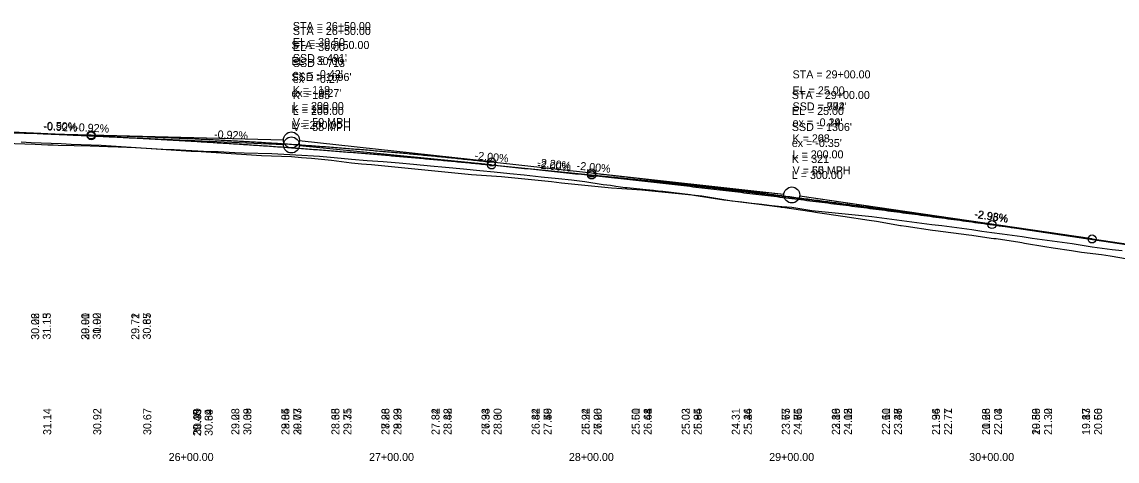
# Model space of a CAD drawing. Extents: x 3880794 to 3915434, y 287517 to 300173.
# Drawn here: x 3883054 to 3883601, y 296520 to 296739 of the extents above; entities that cross this region are included whole.
import ezdxf

# ---------------------------------------------------------------- set-up
doc = ezdxf.new("R2010")
doc.units = 0
for name, color, linetype in [('Level 1', 7, 'Continuous'), ('Level 2', 7, 'Continuous'), ('Level 30', 7, 'Continuous'), ('Level 31', 7, 'Continuous'), ('Level 32', 7, 'Continuous')]:
    doc.layers.add(name, color=color, linetype=linetype)

msp = doc.modelspace()

# ---------------------------------------------------------------- linework, layer by layer
at = {"layer": 'Level 1'}
for p, q in [((3882738.3, 296691.51), (3883088.3, 296682.76)), ((3883088.3, 296682.34), (3882892.29, 296691.32)), ((3883088.3, 296682.76), (3883184.3, 296680.36)), ((3883088.3, 296682.34), (3883184.3, 296677.94)), ((3883288.3, 296669.26), (3883192.27, 296679.82)), ((3883288.3, 296667.76), (3883192.28, 296677.36)), ((3883288.3, 296669.26), (3883338.3, 296663.76)), ((3883288.3, 296667.76), (3883434.32, 296653.16)), ((3883338.3, 296663.76), (3883434.32, 296653.19)), ((3883588.3, 296630.76), (3883442.25, 296652.18)), ((3883538.3, 296637.96), (3883442.25, 296652.17)), ((3883538.3, 296637.96), (3883838.3, 296593.56)), ((3883588.3, 296630.76), (3883838.3, 296594.09))]:
    msp.add_line(p, q, dxfattribs=at)
for points in [[(3883044.95, 296678.6), (3883060.37, 296678.16), (3883066.58, 296677.9), (3883069.37, 296677.82), (3883071.73, 296677.72), (3883087.79, 296677.27), (3883096.62, 296676.93), (3883101.73, 296676.79), (3883110.49, 296676.45), (3883126.78, 296675.58), (3883129.78, 296675.47), (3883147.36, 296674.53)], [(3883147.36, 296674.53), (3883151.71, 296674.52), (3883159.98, 296674.07), (3883164.76, 296673.8), (3883178.49, 296673.55), (3883184.5, 296673.22), (3883190.45, 296672.9), (3883202.4, 296672.11), (3883209.69, 296671.5), (3883218.25, 296670.64), (3883226.17, 296669.98), (3883234.22, 296669.43), (3883242.1, 296668.86), (3883249.28, 296668.2), (3883257.77, 296667.37), (3883265.3, 296666.68), (3883274.32, 296665.85), (3883282.48, 296665.06), (3883289.67, 296664.32), (3883297.39, 296663.48), (3883304.57, 296662.78), (3883313.02, 296661.87), (3883321.71, 296661.06), (3883328.28, 296660.34), (3883334.9, 296659.47), (3883344.06, 296658.03), (3883347.79, 296657.62), (3883350.39, 296657.19), (3883354.97, 296656.56), (3883356.1, 296656.47), (3883365.47, 296655.51), (3883369.23, 296655.18), (3883370.2, 296655.02), (3883371.5, 296654.87), (3883373.81, 296654.65), (3883387.76, 296652.97), (3883389.35, 296652.74), (3883404.31, 296650.42), (3883405.95, 296650.21), (3883419.36, 296648.54), (3883420.71, 296648.42), (3883432.28, 296646.87), (3883432.97, 296646.72), (3883433.28, 296646.69), (3883433.62, 296646.68), (3883448.27, 296644.59), (3883451.1, 296644), (3883463.76, 296642.16), (3883476.86, 296640.13), (3883480.52, 296639.63), (3883492.55, 296637.58), (3883492.91, 296637.53), (3883495.39, 296637.19), (3883508.51, 296635.16), (3883510.04, 296634.96), (3883526.73, 296632.91), (3883528.26, 296632.7), (3883537.81, 296631.24), (3883539.26, 296631.04), (3883540.32, 296630.93), (3883552.14, 296629.21), (3883553.22, 296629.03), (3883554.53, 296628.75), (3883564.71, 296626.94), (3883568.83, 296626.35), (3883577.96, 296624.98), (3883583.07, 296624.19), (3883592.97, 296623.06), (3883597.27, 296622.38), (3883605.94, 296620.85)]]:
    msp.add_lwpolyline(points, dxfattribs=at)
for centre in [(3883188.3, 296680.26), (3883188.3, 296677.76), (3883438.3, 296652.76), (3883438.3, 296652.76)]:
    msp.add_circle(centre, 4, dxfattribs=at)
for points in [[(3882688.3, 296694.36), (3882696.3, 296694.25), (3882704.3, 296694.13), (3882712.3, 296694), (3882720.3, 296693.87), (3882728.3, 296693.73), (3882736.3, 296693.59), (3882744.3, 296693.44), (3882752.3, 296693.29), (3882760.3, 296693.13), (3882768.3, 296692.97), (3882776.3, 296692.8), (3882784.3, 296692.63), (3882792.3, 296692.45), (3882800.3, 296692.27), (3882808.3, 296692.08), (3882816.3, 296691.89), (3882824.3, 296691.69), (3882832.3, 296691.49), (3882840.3, 296691.28), (3882848.3, 296691.07), (3882856.3, 296690.85), (3882864.3, 296690.63), (3882872.3, 296690.4), (3882880.3, 296690.17), (3882888.3, 296689.93), (3882896.3, 296689.69), (3882904.3, 296689.44), (3882912.3, 296689.19), (3882920.3, 296688.93), (3882928.3, 296688.66), (3882936.3, 296688.4), (3882944.3, 296688.12), (3882952.3, 296687.84), (3882960.3, 296687.56), (3882968.3, 296687.27), (3882976.3, 296686.98), (3882984.3, 296686.68), (3882992.3, 296686.38), (3883000.3, 296686.07), (3883008.3, 296685.75), (3883016.3, 296685.44), (3883024.3, 296685.11), (3883032.3, 296684.78), (3883040.3, 296684.45), (3883048.3, 296684.11), (3883056.3, 296683.77), (3883064.3, 296683.42), (3883072.3, 296683.06), (3883080.3, 296682.7), (3883088.3, 296682.34)], [(3883088.3, 296682.76), (3883092.3, 296682.65), (3883096.3, 296682.54), (3883100.3, 296682.43), (3883104.3, 296682.3), (3883108.3, 296682.17), (3883112.3, 296682.03), (3883116.3, 296681.89), (3883120.3, 296681.74), (3883124.3, 296681.58), (3883128.3, 296681.42), (3883132.3, 296681.25), (3883136.3, 296681.07), (3883140.3, 296680.88), (3883144.3, 296680.69), (3883148.3, 296680.49), (3883152.3, 296680.29), (3883156.3, 296680.07), (3883160.3, 296679.86), (3883164.3, 296679.63), (3883168.3, 296679.4), (3883172.3, 296679.16), (3883176.3, 296678.91), (3883180.3, 296678.66), (3883184.3, 296678.4), (3883188.3, 296678.13), (3883192.3, 296677.86), (3883196.3, 296677.58), (3883200.3, 296677.29), (3883204.3, 296677), (3883208.3, 296676.7), (3883212.3, 296676.39), (3883216.3, 296676.08), (3883220.3, 296675.75), (3883224.3, 296675.43), (3883228.3, 296675.09), (3883232.3, 296674.75), (3883236.3, 296674.4), (3883240.3, 296674.05), (3883244.3, 296673.69), (3883248.3, 296673.32), (3883252.3, 296672.94), (3883256.3, 296672.56), (3883260.3, 296672.17), (3883264.3, 296671.77), (3883268.3, 296671.37), (3883272.3, 296670.96), (3883276.3, 296670.55), (3883280.3, 296670.12), (3883284.3, 296669.69), (3883288.3, 296669.26)], [(3883088.3, 296682.34), (3883092.3, 296682.15), (3883096.3, 296681.96), (3883100.3, 296681.77), (3883104.3, 296681.57), (3883108.3, 296681.37), (3883112.3, 296681.16), (3883116.3, 296680.95), (3883120.3, 296680.73), (3883124.3, 296680.51), (3883128.3, 296680.29), (3883132.3, 296680.06), (3883136.3, 296679.83), (3883140.3, 296679.59), (3883144.3, 296679.35), (3883148.3, 296679.1), (3883152.3, 296678.85), (3883156.3, 296678.6), (3883160.3, 296678.34), (3883164.3, 296678.07), (3883168.3, 296677.81), (3883172.3, 296677.53), (3883176.3, 296677.26), (3883180.3, 296676.98), (3883184.3, 296676.69), (3883188.3, 296676.4), (3883192.3, 296676.11), (3883196.3, 296675.81), (3883200.3, 296675.51), (3883204.3, 296675.2), (3883208.3, 296674.89), (3883212.3, 296674.57), (3883216.3, 296674.25), (3883220.3, 296673.93), (3883224.3, 296673.6), (3883228.3, 296673.27), (3883232.3, 296672.93), (3883236.3, 296672.59), (3883240.3, 296672.24), (3883244.3, 296671.89), (3883248.3, 296671.54), (3883252.3, 296671.18), (3883256.3, 296670.82), (3883260.3, 296670.45), (3883264.3, 296670.08), (3883268.3, 296669.7), (3883272.3, 296669.32), (3883276.3, 296668.94), (3883280.3, 296668.55), (3883284.3, 296668.15), (3883288.3, 296667.76)], [(3883288.3, 296667.76), (3883294.3, 296667.15), (3883300.3, 296666.55), (3883306.3, 296665.93), (3883312.3, 296665.31), (3883318.3, 296664.69), (3883324.3, 296664.06), (3883330.3, 296663.42), (3883336.3, 296662.78), (3883342.3, 296662.13), (3883348.3, 296661.48), (3883354.3, 296660.82), (3883360.3, 296660.15), (3883366.3, 296659.48), (3883372.3, 296658.81), (3883378.3, 296658.13), (3883384.3, 296657.44), (3883390.3, 296656.75), (3883396.3, 296656.05), (3883402.3, 296655.35), (3883408.3, 296654.64), (3883414.3, 296653.92), (3883420.3, 296653.2), (3883426.3, 296652.48), (3883432.3, 296651.74), (3883438.3, 296651.01), (3883444.3, 296650.26), (3883450.3, 296649.52), (3883456.3, 296648.76), (3883462.3, 296648), (3883468.3, 296647.24), (3883474.3, 296646.47), (3883480.3, 296645.69), (3883486.3, 296644.91), (3883492.3, 296644.12), (3883498.3, 296643.33), (3883504.3, 296642.53), (3883510.3, 296641.72), (3883516.3, 296640.91), (3883522.3, 296640.1), (3883528.3, 296639.28), (3883534.3, 296638.45), (3883540.3, 296637.62), (3883546.3, 296636.78), (3883552.3, 296635.94), (3883558.3, 296635.09), (3883564.3, 296634.23), (3883570.3, 296633.37), (3883576.3, 296632.51), (3883582.3, 296631.63), (3883588.3, 296630.76)], [(3883338.3, 296663.76), (3883342.3, 296663.32), (3883346.3, 296662.87), (3883350.3, 296662.42), (3883354.3, 296661.97), (3883358.3, 296661.52), (3883362.3, 296661.06), (3883366.3, 296660.6), (3883370.3, 296660.14), (3883374.3, 296659.67), (3883378.3, 296659.2), (3883382.3, 296658.73), (3883386.3, 296658.26), (3883390.3, 296657.78), (3883394.3, 296657.3), (3883398.3, 296656.81), (3883402.3, 296656.33), (3883406.3, 296655.84), (3883410.3, 296655.34), (3883414.3, 296654.85), (3883418.3, 296654.35), (3883422.3, 296653.85), (3883426.3, 296653.34), (3883430.3, 296652.83), (3883434.3, 296652.32), (3883438.3, 296651.81), (3883442.3, 296651.29), (3883446.3, 296650.77), (3883450.3, 296650.25), (3883454.3, 296649.72), (3883458.3, 296649.19), (3883462.3, 296648.66), (3883466.3, 296648.12), (3883470.3, 296647.58), (3883474.3, 296647.04), (3883478.3, 296646.49), (3883482.3, 296645.95), (3883486.3, 296645.4), (3883490.3, 296644.84), (3883494.3, 296644.29), (3883498.3, 296643.72), (3883502.3, 296643.16), (3883506.3, 296642.6), (3883510.3, 296642.03), (3883514.3, 296641.45), (3883518.3, 296640.88), (3883522.3, 296640.3), (3883526.3, 296639.72), (3883530.3, 296639.13), (3883534.3, 296638.55), (3883538.3, 296637.96)]]:
    msp.add_spline(points, degree=3, dxfattribs=at)
at = {"layer": 'Level 2'}
for p, q in [((3883038.3, 296684.63), (3883088.3, 296682.34)), ((3883088.3, 296682.34), (3883184.3, 296677.94)), ((3883288.3, 296667.76), (3883192.28, 296677.36)), ((3883288.3, 296667.76), (3883338.3, 296662.76)), ((3883338.3, 296662.76), (3883434.32, 296653.16)), ((3883538.3, 296637.96), (3883442.25, 296652.17)), ((3883538.3, 296637.96), (3883838.3, 296593.56))]:
    msp.add_line(p, q, dxfattribs=at)
for points in [[(3883053.3, 296679.3), (3883058.3, 296679.08), (3883063.3, 296678.87), (3883068.3, 296678.66), (3883073.3, 296678.44), (3883078.3, 296678.22), (3883083.3, 296678.01), (3883088.3, 296677.8), (3883093.3, 296677.59), (3883098.3, 296677.33), (3883103.3, 296677.01), (3883108.3, 296676.69), (3883113.3, 296676.37), (3883118.3, 296676.05), (3883123.3, 296675.72), (3883128.3, 296675.4), (3883133.3, 296675.07), (3883138.3, 296674.75), (3883143.3, 296674.43), (3883148.3, 296674.1), (3883153.3, 296673.78), (3883158.3, 296673.46), (3883163.3, 296673.14), (3883168.3, 296672.82), (3883173.3, 296672.53), (3883178.3, 296672.34), (3883183.3, 296672.16), (3883188.3, 296671.96), (3883193.3, 296671.54), (3883198.3, 296671.12), (3883203.3, 296670.7), (3883208.3, 296670.13), (3883213.3, 296669.51), (3883218.3, 296668.9), (3883223.3, 296668.35), (3883228.3, 296667.93), (3883233.3, 296667.5), (3883238.3, 296667.08), (3883243.3, 296666.58), (3883248.3, 296666.05), (3883253.3, 296665.52), (3883258.3, 296665), (3883263.3, 296664.48), (3883268.3, 296663.96), (3883273.3, 296663.44), (3883278.3, 296663.09), (3883283.3, 296662.74), (3883288.3, 296662.39), (3883293.3, 296661.97), (3883298.3, 296661.47), (3883303.3, 296660.98), (3883308.3, 296660.48), (3883313.3, 296659.96), (3883318.3, 296659.43), (3883323.3, 296658.89), (3883328.3, 296658.36), (3883333.3, 296657.85), (3883338.3, 296657.35), (3883343.3, 296656.85), (3883348.3, 296656.35), (3883353.3, 296655.99), (3883358.3, 296655.68), (3883363.3, 296655.3), (3883368.3, 296654.84), (3883373.3, 296654.37), (3883378.3, 296653.89), (3883383.3, 296653.38), (3883388.3, 296652.88), (3883393.3, 296652.32), (3883398.3, 296651.51), (3883403.3, 296650.69), (3883408.3, 296649.92), (3883413.3, 296649.32), (3883418.3, 296648.72), (3883423.3, 296648.12), (3883428.3, 296647.52), (3883433.3, 296647.07), (3883438.3, 296646.63), (3883443.3, 296645.8), (3883448.3, 296645.03), (3883453.3, 296644.52), (3883458.3, 296644.04), (3883463.3, 296643.56), (3883468.3, 296643.07), (3883473.3, 296642.51), (3883478.3, 296641.93), (3883483.3, 296641.35), (3883488.3, 296640.75), (3883493.3, 296640.05), (3883498.3, 296639.35), (3883503.3, 296638.67), (3883508.3, 296638.03), (3883513.3, 296637.44), (3883518.3, 296636.85), (3883523.3, 296636.17), (3883528.3, 296635.46), (3883533.3, 296634.75), (3883538.3, 296634.04)], [(3883538.3, 296634.04), (3883543.3, 296633.42), (3883548.3, 296632.7), (3883553.3, 296631.98), (3883558.3, 296631.22), (3883563.3, 296630.54), (3883568.3, 296629.86), (3883573.3, 296629.19), (3883578.3, 296628.47), (3883583.3, 296627.69), (3883588.3, 296626.91), (3883593.3, 296626.1), (3883598.3, 296625.49), (3883603.3, 296624.93)]]:
    msp.add_lwpolyline(points, dxfattribs=at)
for centre, radius in [((3883088.3, 296682.34), 2), ((3883188.3, 296677.76), 4), ((3883288.3, 296667.76), 2), ((3883338.3, 296662.76), 2), ((3883438.3, 296652.76), 4), ((3883538.3, 296637.96), 2)]:
    msp.add_circle(centre, radius, dxfattribs=at)
for points in [[(3883088.3, 296682.34), (3883092.3, 296682.15), (3883096.3, 296681.96), (3883100.3, 296681.77), (3883104.3, 296681.57), (3883108.3, 296681.37), (3883112.3, 296681.16), (3883116.3, 296680.95), (3883120.3, 296680.73), (3883124.3, 296680.51), (3883128.3, 296680.29), (3883132.3, 296680.06), (3883136.3, 296679.83), (3883140.3, 296679.59), (3883144.3, 296679.35), (3883148.3, 296679.1), (3883152.3, 296678.85), (3883156.3, 296678.6), (3883160.3, 296678.34), (3883164.3, 296678.07), (3883168.3, 296677.81), (3883172.3, 296677.53), (3883176.3, 296677.26), (3883180.3, 296676.98), (3883184.3, 296676.69), (3883188.3, 296676.4), (3883192.3, 296676.11), (3883196.3, 296675.81), (3883200.3, 296675.51), (3883204.3, 296675.2), (3883208.3, 296674.89), (3883212.3, 296674.57), (3883216.3, 296674.25), (3883220.3, 296673.93), (3883224.3, 296673.6), (3883228.3, 296673.27), (3883232.3, 296672.93), (3883236.3, 296672.59), (3883240.3, 296672.24), (3883244.3, 296671.89), (3883248.3, 296671.54), (3883252.3, 296671.18), (3883256.3, 296670.82), (3883260.3, 296670.45), (3883264.3, 296670.08), (3883268.3, 296669.7), (3883272.3, 296669.32), (3883276.3, 296668.94), (3883280.3, 296668.55), (3883284.3, 296668.15), (3883288.3, 296667.76)], [(3883338.3, 296662.76), (3883342.3, 296662.36), (3883346.3, 296661.95), (3883350.3, 296661.54), (3883354.3, 296661.13), (3883358.3, 296660.71), (3883362.3, 296660.29), (3883366.3, 296659.86), (3883370.3, 296659.43), (3883374.3, 296659), (3883378.3, 296658.56), (3883382.3, 296658.12), (3883386.3, 296657.68), (3883390.3, 296657.23), (3883394.3, 296656.78), (3883398.3, 296656.32), (3883402.3, 296655.87), (3883406.3, 296655.4), (3883410.3, 296654.93), (3883414.3, 296654.46), (3883418.3, 296653.99), (3883422.3, 296653.51), (3883426.3, 296653.03), (3883430.3, 296652.54), (3883434.3, 296652.05), (3883438.3, 296651.56), (3883442.3, 296651.06), (3883446.3, 296650.56), (3883450.3, 296650.05), (3883454.3, 296649.54), (3883458.3, 296649.03), (3883462.3, 296648.51), (3883466.3, 296647.99), (3883470.3, 296647.47), (3883474.3, 296646.94), (3883478.3, 296646.4), (3883482.3, 296645.87), (3883486.3, 296645.33), (3883490.3, 296644.78), (3883494.3, 296644.24), (3883498.3, 296643.68), (3883502.3, 296643.13), (3883506.3, 296642.57), (3883510.3, 296642.01), (3883514.3, 296641.44), (3883518.3, 296640.87), (3883522.3, 296640.29), (3883526.3, 296639.72), (3883530.3, 296639.13), (3883534.3, 296638.55), (3883538.3, 296637.96)]]:
    msp.add_spline(points, degree=3, dxfattribs=at)
at = {"layer": 'Level 31'}
for centre in [(3883088.3, 296682.76), (3883088.3, 296682.34), (3883088.3, 296682.34), (3883288.3, 296669.26), (3883288.3, 296667.76), (3883288.3, 296667.76), (3883338.3, 296663.76), (3883538.3, 296637.96), (3883588.3, 296630.76)]:
    msp.add_circle(centre, 2, dxfattribs=at)

# ---------------------------------------------------------------- texts
at = {"layer": 'Level 2'}
for s, p in [('STA = 26+50.00', (3883189.03, 296732.75)), ('EL = 30.00', (3883189.03, 296724.75)), ("SSD = 713'", (3883189.03, 296716.75)), ('STA = 29+00.00', (3883438.67, 296711.07)), ("ex = -0.27'", (3883189.03, 296708.75)), ('K = 185', (3883189.03, 296700.75)), ('EL = 25.00', (3883438.67, 296703.07)), ("SSD = 792'", (3883438.67, 296695.07)), ('L = 200.00', (3883189.03, 296692.75)), ('V = 55 MPH', (3883189.03, 296684.75)), ("ex = -0.24'", (3883438.67, 296687.07)), ('K = 208', (3883438.67, 296679.07)), ('L = 200.00', (3883438.67, 296671.07)), ('V = 55 MPH', (3883438.67, 296663.07)), ('26+00.00', (3883126.99, 296519.76)), ('27+00.00', (3883227.09, 296519.76)), ('28+00.00', (3883326.93, 296519.76)), ('29+00.00', (3883426.99, 296519.76)), ('30+00.00', (3883526.9, 296519.76))]:
    msp.add_text(s, height=4, dxfattribs=at).set_placement(p)
for s, rotation, p in [('-0.92%', 357.3758, (3883064.41, 296685.15)), ('-0.92%', 357.3758, (3883149.6, 296681.2)), ('-2.00%', 354.2894, (3883310.93, 296666.08)), ('-2.96%', 351.5813, (3883529.38, 296641.3)), ('31.15', 90, (3883068.09, 296580.49)), ('30.92', 90, (3883093.09, 296580.49)), ('30.67', 90, (3883118.09, 296580.49)), ('30.39', 90, (3883148.97, 296532.3)), ('30.08', 90, (3883168.3, 296532.76)), ('29.73', 90, (3883193.3, 296532.76)), ('29.35', 90, (3883218.3, 296532.76)), ('28.93', 90, (3883243.3, 296532.76)), ('28.48', 90, (3883268.3, 296532.76)), ('28.00', 90, (3883293.3, 296532.76)), ('27.50', 90, (3883318.3, 296532.76)), ('27.00', 90, (3883343.3, 296532.76)), ('26.48', 90, (3883368.3, 296532.76)), ('25.94', 90, (3883393.3, 296532.76)), ('25.36', 90, (3883418.3, 296532.76)), ('24.76', 90, (3883443.3, 296532.76)), ('24.13', 90, (3883468.3, 296532.76)), ('23.46', 90, (3883493.3, 296532.76)), ('22.77', 90, (3883518.3, 296532.76)), ('22.04', 90, (3883543.3, 296532.76)), ('21.30', 90, (3883568.3, 296532.76)), ('20.56', 90, (3883593.3, 296532.76))]:
    msp.add_text(s, height=4, rotation=rotation, dxfattribs=at).set_placement(p)
at = {"layer": 'Level 30'}
for s, p in [('30.06', (3883062.3, 296580.35)), ('29.90', (3883087.3, 296580.35)), ('29.71', (3883112.3, 296580.35)), ('29.45', (3883143.18, 296532.17)), ('29.23', (3883162.3, 296532.76)), ('29.05', (3883187.3, 296532.76)), ('28.68', (3883212.3, 296532.76)), ('28.28', (3883237.3, 296532.76)), ('27.82', (3883262.3, 296532.76)), ('27.34', (3883287.3, 296532.76)), ('26.82', (3883312.3, 296532.76)), ('26.24', (3883337.3, 296532.76)), ('25.60', (3883362.3, 296532.76)), ('25.03', (3883387.3, 296532.76)), ('24.31', (3883412.3, 296532.76)), ('23.65', (3883437.3, 296532.76)), ('22.89', (3883462.3, 296532.76)), ('22.11', (3883487.3, 296532.76)), ('21.36', (3883512.3, 296532.76)), ('20.68', (3883537.3, 296532.76)), ('19.89', (3883562.3, 296532.76)), ('19.17', (3883587.3, 296532.76))]:
    msp.add_text(s, height=4, rotation=90, dxfattribs=at).set_placement(p)
for s, p in [('26+00.00', (3883126.99, 296519.76)), ('26+00.00', (3883126.99, 296519.76)), ('26+00.00', (3883126.99, 296519.76)), ('27+00.00', (3883227.09, 296519.76)), ('27+00.00', (3883227.09, 296519.76)), ('27+00.00', (3883227.09, 296519.76)), ('28+00.00', (3883326.93, 296519.76)), ('28+00.00', (3883326.93, 296519.76)), ('28+00.00', (3883326.93, 296519.76)), ('29+00.00', (3883426.99, 296519.76)), ('29+00.00', (3883426.99, 296519.76)), ('29+00.00', (3883426.99, 296519.76)), ('30+00.00', (3883526.9, 296519.76)), ('30+00.00', (3883526.9, 296519.76)), ('30+00.00', (3883526.9, 296519.76))]:
    msp.add_text(s, height=4, dxfattribs=at).set_placement(p)
at = {"layer": 'Level 31'}
for s, p in [('STA = 26+50.00', (3883189.03, 296735.25)), ('EL = 30.50', (3883189.03, 296727.25)), ('STA = 26+50.00', (3883188.3, 296725.76)), ('EL = 30.00', (3883188.3, 296717.76)), ("SSD = 491'", (3883189.03, 296719.25)), ("ex = -0.42'", (3883189.03, 296711.25)), ('STA = 29+00.00', (3883438.67, 296711.07)), ("SSD = 1096'", (3883188.3, 296709.76)), ("ex = -0.27'", (3883188.3, 296701.76)), ('K = 118', (3883189.03, 296703.25)), ('STA = 29+00.00', (3883438.3, 296700.76)), ('EL = 25.00', (3883438.67, 296703.07)), ('K = 185', (3883188.3, 296693.76)), ('L = 200.00', (3883189.03, 296695.25)), ("SSD = 974'", (3883438.67, 296695.07)), ('EL = 25.00', (3883438.3, 296692.76)), ('L = 200.00', (3883188.3, 296685.76)), ('V = 50 MPH', (3883189.03, 296687.25)), ("SSD = 1306'", (3883438.3, 296684.76)), ("ex = -0.19'", (3883438.67, 296687.07)), ('K = 263', (3883438.67, 296679.07)), ("ex = -0.35'", (3883438.3, 296676.76)), ('K = 321', (3883438.3, 296668.76)), ('L = 200.00', (3883438.67, 296671.07)), ('V = 60 MPH', (3883438.67, 296663.07)), ('L = 300.00', (3883438.3, 296660.76))]:
    msp.add_text(s, height=4, dxfattribs=at).set_placement(p)
for s, rotation, p in [('-0.50%', 358.5679, (3883064.29, 296685.4)), ('-0.92%', 357.3758, (3883080.22, 296684.71)), ('-2.00%', 354.2894, (3883279.7, 296670.63)), ('-2.20%', 353.7227, (3883310.93, 296667.16)), ('-2.00%', 354.2894, (3883330.69, 296665.53)), ('-2.93%', 351.6561, (3883529.18, 296641.45)), ('-2.96%', 351.5813, (3883529.38, 296641.3)), ('31.13', 90, (3883068.09, 296580.49)), ('31.00', 90, (3883093.09, 296580.49)), ('30.85', 90, (3883118.09, 296580.49)), ('31.14', 90, (3883068.3, 296532.76)), ('30.92', 90, (3883093.3, 296532.76)), ('30.67', 90, (3883118.3, 296532.76)), ('30.39', 90, (3883143.3, 296532.76)), ('30.64', 90, (3883148.97, 296532.3)), ('30.08', 90, (3883168.3, 296532.76)), ('30.39', 90, (3883168.3, 296532.76)), ('29.73', 90, (3883193.3, 296532.76)), ('30.07', 90, (3883193.3, 296532.76)), ('29.35', 90, (3883218.3, 296532.76)), ('29.71', 90, (3883218.3, 296532.76)), ('28.93', 90, (3883243.3, 296532.76)), ('29.29', 90, (3883243.3, 296532.76)), ('28.48', 90, (3883268.3, 296532.76)), ('28.82', 90, (3883268.3, 296532.76)), ('28.30', 90, (3883293.3, 296532.76)), ('28.00', 90, (3883293.3, 296532.76)), ('27.75', 90, (3883318.3, 296532.76)), ('27.49', 90, (3883318.3, 296532.76)), ('27.20', 90, (3883343.3, 296532.76)), ('26.96', 90, (3883343.3, 296532.76)), ('26.64', 90, (3883368.3, 296532.76)), ('26.41', 90, (3883368.3, 296532.76)), ('25.84', 90, (3883393.3, 296532.76)), ('26.05', 90, (3883393.3, 296532.76)), ('25.44', 90, (3883418.3, 296532.76)), ('25.26', 90, (3883418.3, 296532.76)), ('24.65', 90, (3883443.3, 296532.76)), ('24.81', 90, (3883443.3, 296532.76)), ('24.15', 90, (3883468.3, 296532.76)), ('24.02', 90, (3883468.3, 296532.76)), ('23.38', 90, (3883493.3, 296532.76)), ('23.47', 90, (3883493.3, 296532.76)), ('22.71', 90, (3883518.3, 296532.76)), ('22.77', 90, (3883518.3, 296532.76)), ('22.04', 90, (3883543.3, 296532.76)), ('22.03', 90, (3883543.3, 296532.76)), ('21.30', 90, (3883568.3, 296532.76)), ('21.32', 90, (3883568.3, 296532.76)), ('20.60', 90, (3883593.3, 296532.76)), ('20.56', 90, (3883593.3, 296532.76))]:
    msp.add_text(s, height=4, rotation=rotation, dxfattribs=at).set_placement(p)
at = {"layer": 'Level 32'}
for s, p in [('30.22', (3883062.3, 296580.35)), ('30.01', (3883087.3, 296580.35)), ('29.72', (3883112.3, 296580.35)), ('29.40', (3883143.18, 296532.17)), ('29.08', (3883162.3, 296532.76)), ('28.84', (3883187.3, 296532.76)), ('28.35', (3883212.3, 296532.76)), ('27.86', (3883237.3, 296532.76)), ('27.34', (3883262.3, 296532.76)), ('26.93', (3883287.3, 296532.76)), ('26.44', (3883312.3, 296532.76)), ('25.92', (3883337.3, 296532.76)), ('25.51', (3883362.3, 296532.76)), ('25.02', (3883387.3, 296532.76)), ('24.31', (3883412.3, 296532.76)), ('23.77', (3883437.3, 296532.76)), ('23.16', (3883462.3, 296532.76)), ('22.60', (3883487.3, 296532.76)), ('21.94', (3883512.3, 296532.76)), ('21.26', (3883537.3, 296532.76)), ('20.56', (3883562.3, 296532.76)), ('19.83', (3883587.3, 296532.76))]:
    msp.add_text(s, height=4, rotation=90, dxfattribs=at).set_placement(p)

doc.saveas('drawing.dxf')
